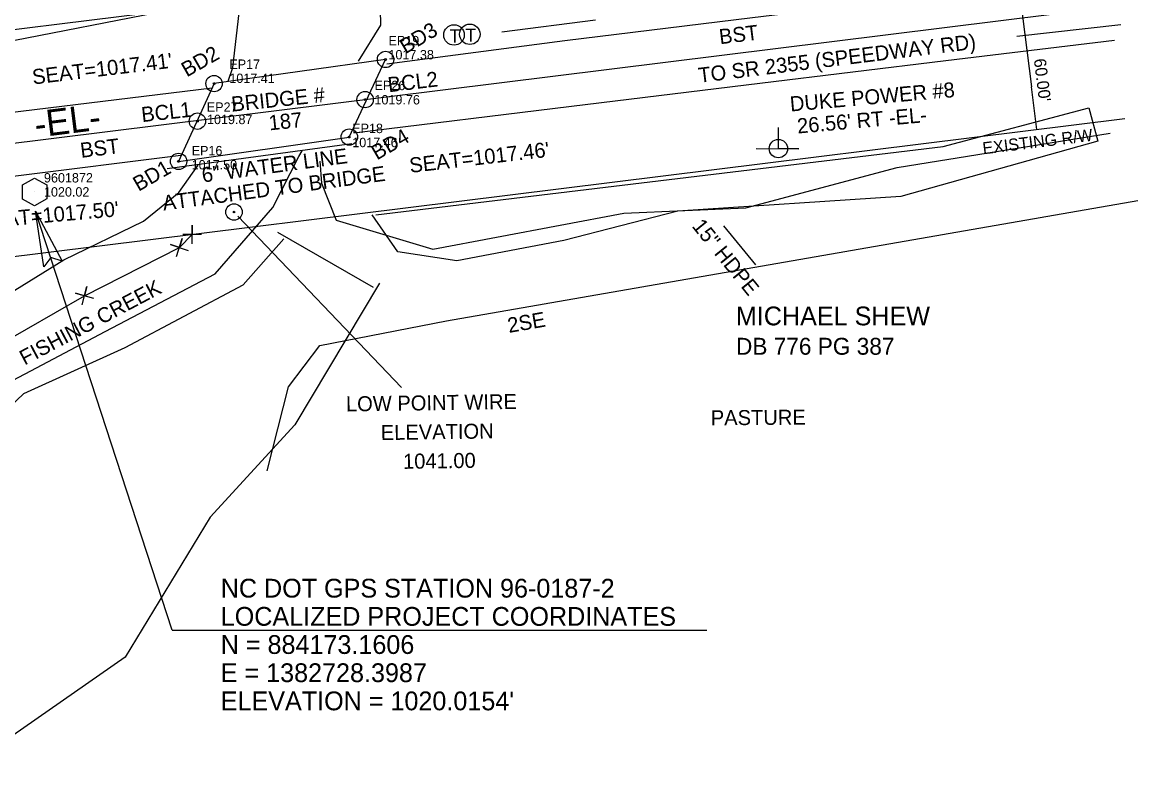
# Model space of a CAD drawing. Extents: x 1382088 to 1383563, y 883989 to 884716.
# Drawn here: x 1382725.1 to 1383021.8, y 884019.9 to 884218.3 of the extents above; entities that cross this region are included whole.
import ezdxf

# ---------------------------------------------------------------- set-up
doc = ezdxf.new("R2010")
doc.units = 0
for name, color, linetype in [('CTL GPS Vertical CELL', 7, 'Continuous'), ('CTL GPS Vertical Cogo Elevation', 7, 'Continuous'), ('CTL GPS Vertical Cogo Number', 7, 'Continuous'), ('CTL GPS Vertical Text', 7, 'Continuous'), ('Default', 7, 'Continuous'), ('Exist DTM Regular Point Cogo Elevation', 7, 'Continuous'), ('Exist DTM Regular Point Cogo Number', 7, 'Continuous'), ('Exist Horizontal Alignment', 7, 'Continuous'), ('Exist Horizontal Alignment Direction Label', 7, 'Continuous'), ('Exist Hydro Jurisdictional Stream or Body of Water', 7, 'Continuous'), ('Exist Hydro Jurisdictional Stream or Body of Water Text', 7, 'Continuous'), ('Exist Hydro Stream or Body of Water', 7, 'Continuous'), ('Exist Other Culture Fence Line', 7, 'Continuous'), ('Exist Other Culture Fence Line Text', 7, 'Continuous'), ('Exist Other Culture Located Object CELL', 7, 'Continuous'), ('Exist Other Culture Located Object Text', 7, 'Continuous'), ('Exist Property Corner CELL', 7, 'Continuous'), ('Exist Property Deed Book Text', 7, 'Continuous'), ('Exist Property Line', 7, 'Continuous'), ('Exist Property Owner Text', 7, 'Continuous'), ('Exist Right of Way Line', 7, 'Continuous'), ('Exist Right of Way Line Text', 7, 'Continuous'), ('Exist Right of Way Width CELL', 7, 'Continuous'), ('Exist Roads EOP', 7, 'Continuous'), ('Exist Roads EOP Leader', 7, 'Continuous'), ('Exist Roads EOP Text', 7, 'Continuous'), ('Exist Structure Major Bridge Seat Top Elevation', 7, 'Continuous'), ('Exist Structure Major Deck Tunnel Box Culvert', 7, 'Continuous'), ('Exist Structure Major Deck Tunnel Box Culvert Text', 7, 'Continuous'), ('Exist Structure Minor Pipes HDPE 15 Inch', 7, 'Continuous'), ('Exist Structure Minor Pipes HDPE 15 Inch Text', 7, 'Continuous'), ('Exist Utilities Other Located Object CELL', 7, 'Continuous'), ('Exist Utilities Other Located Object Leader', 7, 'Continuous'), ('Exist Utilities Other Located Object Text', 7, 'Continuous'), ('Exist Utilities Power Joint Use Telephone CELL', 7, 'Continuous'), ('Exist Utilities Power Joint Use Telephone Text', 7, 'Continuous'), ('Exist Utilities Sanitary Sewer Manhole Cogo Elevation', 7, 'Continuous'), ('Exist Utilities Sanitary Sewer Manhole Cogo Number', 7, 'Continuous'), ('Exist Utilities Telephone Manhole CELL', 7, 'Continuous'), ('Exist Utilities Telephone UG FO', 7, 'Continuous'), ('Exist Utilities Water AG Line', 7, 'Continuous'), ('Exist Utilities Water AG Line Text', 7, 'Continuous'), ('Exist Vegetation Woods Line', 7, 'Continuous'), ('Exist Vegetation Woods Line Text', 7, 'Continuous'), ('Old_Level_11', 7, 'Continuous')]:
    doc.layers.add(name, color=color, linetype=linetype)

# ---------------------------------------------------------------- blocks, each defined once
blk = doc.blocks.new('EXIST OTHER CULTURE LOCATED OBJECT')
at = {"layer": 'Exist Other Culture Located Object CELL'}
for radius in [0.0436, 0.0048]:
    blk.add_circle((0, 0), radius, dxfattribs=at)

msp = doc.modelspace()

# ---------------------------------------------------------------- linework, layer by layer
at = {"layer": 'CTL GPS Vertical CELL'}
msp.add_line((1382728.4, 884173.16), (1382728.4, 884173.16), dxfattribs=at)
msp.add_lwpolyline([(1382725.17, 884175.03), (1382728.42, 884176.84), (1382731.67, 884175.06), (1382731.62, 884171.33), (1382728.37, 884169.44), (1382725.17, 884171.26)], close=True, dxfattribs=at)
at = {"layer": 'Default'}
for q in [(1382728.65, 884168.01), (1382907.24, 884056.51)]:
    msp.add_line((1382764.99, 884056.51), q, dxfattribs=at)
at = {"layer": 'Exist Horizontal Alignment'}
msp.add_line((1382573.21, 884167.56), (1383014.71, 884222.44), dxfattribs=at)
at = {"layer": 'Exist Hydro Jurisdictional Stream or Body of Water'}
for points in [[(1382779.86, 884202.64), (1382781.14, 884206.31), (1382784.29, 884233.98), (1382796.55, 884263.54), (1382815.75, 884285.03)], [(1382814.54, 884207.97), (1382820.54, 884217.58), (1382820.04, 884238.41), (1382839.31, 884257.77), (1382850.16, 884274.58)], [(1382697.09, 884084.7), (1382707.03, 884107.53), (1382718.1, 884120.62), (1382747.18, 884136), (1382776.41, 884151.32), (1382791.76, 884168.97), (1382798.67, 884182.57), (1382799.6, 884184.06)], [(1382676.1, 884092.45), (1382689.38, 884112.63), (1382706.34, 884136.61), (1382736.2, 884155.04), (1382757.42, 884165.36), (1382766.78, 884172.98), (1382771.88, 884180.29)]]:
    msp.add_lwpolyline(points, dxfattribs=at)
at = {"layer": 'Exist Hydro Stream or Body of Water'}
msp.add_lwpolyline([(1382804.25, 884181.32), (1382804.73, 884175.5), (1382808.66, 884165.61), (1382834.38, 884157.94), (1382885.17, 884167.47), (1382917.56, 884168.91), (1382957.83, 884179.68), (1383014.49, 884188.81)], dxfattribs=at)
at = {"layer": 'Exist Other Culture Fence Line'}
msp.add_lwpolyline([(1382790.26, 884098.9), (1382795.98, 884121.25), (1382804.31, 884132.3), (1382837.93, 884138.79), (1383021.83, 884170.84)], dxfattribs=at)
at = {"layer": 'Exist Property Corner CELL'}
for p, q in [((1382770.33, 884161.83), (1382770.33, 884161.83)), ((1382766.92, 884158.34), (1382766.92, 884158.34)), ((1382741.69, 884145.52), (1382741.69, 884145.52))]:
    msp.add_line(p, q, dxfattribs=at)
for points in [[(1382770.36, 884159.33), (1382770.3, 884164.33), (1382770.33, 884161.83), (1382767.83, 884161.8), (1382772.83, 884161.86)], [(1382766.14, 884155.96), (1382767.69, 884160.72), (1382766.92, 884158.34), (1382764.54, 884159.12), (1382769.29, 884157.57)], [(1382741.03, 884143.11), (1382742.34, 884147.93), (1382741.69, 884145.52), (1382739.27, 884146.17), (1382744.1, 884144.86)]]:
    msp.add_lwpolyline(points, dxfattribs=at)
at = {"layer": 'Exist Property Line'}
for p, q in [((1382766.92, 884158.34), (1382770.33, 884161.83)), ((1382741.69, 884145.52), (1382766.92, 884158.34)), ((1382712.22, 884128.62), (1382741.69, 884145.52))]:
    msp.add_line(p, q, dxfattribs=at)
at = {"layer": 'Exist Right of Way Line'}
for p, q in [((1382569.51, 884197.33), (1383011.01, 884252.21)), ((1382576.91, 884137.79), (1383018.41, 884192.67))]:
    msp.add_line(p, q, dxfattribs=at)
at = {"layer": 'Exist Right of Way Width CELL'}
for p in [(1382987.58, 884249.3), (1382994.98, 884189.76)]:
    msp.add_line(p, (1382993.57, 884201.1), dxfattribs=at)
at = {"layer": 'Exist Roads EOP'}
for points in [[(1382822.11, 884207.29), (1382869.48, 884213.43), (1382919.36, 884219.54), (1382969.37, 884225.7), (1383013.63, 884231.16)], [(1382813.33, 884188.87), (1382871.2, 884195.99), (1382921.29, 884202.13), (1382970.84, 884208.1), (1383015.68, 884213.51)], [(1382572.45, 884176.87), (1382622.03, 884182.5), (1382672.6, 884188.52), (1382721.14, 884194.24), (1382775.67, 884200.85)], [(1382574.09, 884158.95), (1382623.82, 884164.93), (1382674.58, 884171.14), (1382723.43, 884177.39), (1382767.31, 884182.9)]]:
    msp.add_lwpolyline(points, dxfattribs=at)
at = {"layer": 'Exist Roads EOP Leader'}
msp.add_line((1383017.33, 884217.65), (1382989.66, 884214.49), dxfattribs=at)
at = {"layer": 'Exist Structure Major Deck Tunnel Box Culvert'}
msp.add_lwpolyline([(1382766.7, 884181.28), (1382812.12, 884187.76), (1382821.76, 884208.41), (1382776.14, 884201.99), (1382766.7, 884181.28)], dxfattribs=at)
at = {"layer": 'Exist Structure Minor Pipes HDPE 15 Inch'}
msp.add_lwpolyline([(1382911.65, 884164.16), (1382920.14, 884153.71)], dxfattribs=at)
at = {"layer": 'Exist Utilities Other Located Object CELL'}
for radius in [2.18, 0.24]:
    msp.add_circle((1382781.45, 884167.8), radius, dxfattribs=at)
at = {"layer": 'Exist Utilities Other Located Object Leader'}
msp.add_line((1382782.46, 884166.68), (1382826.04, 884121.05), dxfattribs=at)
at = {"layer": 'Exist Utilities Power Joint Use Telephone CELL'}
msp.add_line((1382926.26, 884184.67), (1382926.26, 884184.67), dxfattribs=at)
msp.add_lwpolyline([(1382920.32, 884184.67), (1382931.66, 884184.63), (1382926.26, 884184.65), (1382926.26, 884190.29)], dxfattribs=at)
msp.add_circle((1382926.26, 884184.68), 2.45, dxfattribs=at)
at = {"layer": 'Exist Utilities Telephone Manhole CELL'}
for centre in [(1382839.97, 884214.93), (1382844.18, 884215.11)]:
    msp.add_circle(centre, 2.72, dxfattribs=at)
at = {"layer": 'Exist Utilities Telephone UG FO'}
msp.add_lwpolyline([(1382852.69, 884215.72), (1382877.65, 884218.96)], dxfattribs=at)
at = {"layer": 'Exist Utilities Water AG Line'}
msp.add_line((1382763.71, 884179.41), (1382812.76, 884186.01), dxfattribs=at)
at = {"layer": 'Exist Vegetation Woods Line'}
for points in [[(1382816.76, 884294.12), (1382787.84, 884262.24), (1382774.61, 884223.48), (1382708.95, 884210.73), (1382567.82, 884198.87)], [(1382819.17, 884167.05), (1382970.1, 884185.2), (1383008.81, 884195.5), (1383011.26, 884186.67), (1382958.83, 884171.95), (1382899.53, 884168.03), (1382869.15, 884160.18), (1382840.73, 884154.78), (1382825.05, 884157.24), (1382818.19, 884167.05)], [(1382793.02, 884162.47), (1382818.5, 884147.76)], [(1382696.17, 884069.92), (1382708.42, 884103.27), (1382725.57, 884119.46), (1382752.52, 884131.73), (1382783.89, 884148.41), (1382794.67, 884160.67)], [(1382820.15, 884148.9), (1382797.61, 884111.12), (1382775.07, 884086.6), (1382752.52, 884049.31), (1382718.71, 884025.77), (1382700.09, 884019.88)]]:
    msp.add_lwpolyline(points, dxfattribs=at)
at = {"layer": 'Old_Level_11'}
msp.add_lwpolyline([(1382730.84, 884153.21), (1382728.65, 884168.01), (1382735.77, 884154.74), (1382732.69, 884155.71)], close=True, dxfattribs=at)

# ---------------------------------------------------------------- block references
at = {"layer": 'Exist Other Culture Located Object CELL', "xscale": 50, "yscale": 50}
for p in [(1382821.76, 884208.41), (1382776.14, 884201.99), (1382816.33, 884197.73), (1382771.71, 884191.98), (1382812.12, 884187.76), (1382766.7, 884181.28)]:
    msp.add_blockref('EXIST OTHER CULTURE LOCATED OBJECT', p, dxfattribs=at)

# ---------------------------------------------------------------- texts
at = {"layer": 'CTL GPS Vertical Cogo Elevation'}
msp.add_text('1020.02', height=2.5, dxfattribs=at).set_placement((1382730.9, 884171.91))
at = {"layer": 'CTL GPS Vertical Cogo Number'}
msp.add_text('9601872', height=2.5, dxfattribs=at).set_placement((1382730.9, 884175.66))
at = {"layer": 'CTL GPS Vertical Text'}
for s, p in [('NC DOT GPS STATION 96-0187-2', (1382777.92, 884065.17)), ('LOCALIZED PROJECT COORDINATES', (1382777.92, 884057.67)), ('N = 884173.1606', (1382777.92, 884050.17)), ('E = 1382728.3987', (1382777.92, 884042.67)), ("ELEVATION = 1020.0154'", (1382777.92, 884035.17))]:
    msp.add_text(s, height=5, rotation=359.9944, dxfattribs=at).set_placement(p)
at = {"layer": 'Exist DTM Regular Point Cogo Elevation'}
for s, p in [('1019.76', (1382818.81, 884196.44)), ('1019.87', (1382774.27, 884191.2))]:
    msp.add_text(s, height=2.5, dxfattribs=at).set_placement(p)
at = {"layer": 'Exist DTM Regular Point Cogo Number'}
for s, p in [('EP26', (1382818.84, 884200.24)), ('EP27', (1382774.21, 884194.48))]:
    msp.add_text(s, height=2.5, dxfattribs=at).set_placement(p)
at = {"layer": 'Exist Horizontal Alignment Direction Label'}
msp.add_text('-EL-', height=7, rotation=7.0864, dxfattribs=at).set_placement((1382728.79, 884187.58))
at = {"layer": 'Exist Hydro Jurisdictional Stream or Body of Water Text'}
msp.add_text('FISHING CREEK', height=4, rotation=27.8639, dxfattribs=at).set_placement((1382725.75, 884126.93))
at = {"layer": 'Exist Other Culture Fence Line Text'}
msp.add_text('2SE', height=4, rotation=9.8862, dxfattribs=at).set_placement((1382854.59, 884135.61))
at = {"layer": 'Exist Other Culture Located Object Text'}
for s, rotation, p in [('BD3', 30.7884, (1382827.06, 884209.78)), ('BD2', 29.7996, (1382768.91, 884203.62)), ('BCL2', 6.8455, (1382822.61, 884199.67)), ('BCL1', 6.2542, (1382757.01, 884191.72)), ('BD4', 30.1447, (1382819.47, 884181.51)), ('BD1', 30.0713, (1382756.06, 884173.17))]:
    msp.add_text(s, height=4, rotation=rotation, dxfattribs=at).set_placement(p)
at = {"layer": 'Exist Property Deed Book Text'}
msp.add_text('DB 776 PG 387', height=4.5, rotation=0, dxfattribs=at).set_placement((1382914.98, 884129.81))
at = {"layer": 'Exist Property Owner Text'}
msp.add_text('MICHAEL SHEW', height=5, rotation=0, dxfattribs=at).set_placement((1382914.95, 884137.63))
at = {"layer": 'Exist Right of Way Line Text'}
msp.add_text('EXISTING R/W', height=3.2, rotation=7.0864, dxfattribs=at).set_placement((1382980.76, 884183.15))
at = {"layer": 'Exist Right of Way Width CELL'}
msp.add_text("60.00'", height=3.2, rotation=277.0864, dxfattribs=at).set_placement((1382994.19, 884208.46))
at = {"layer": 'Exist Roads EOP Text'}
for s, rotation, p in [('TO SR 2355 (SPEEDWAY RD)', 7.0223, (1382905.23, 884202.18)), ('BST', 6.8712, (1382910.73, 884212.45)), ('BST', 6.9719, (1382740.8, 884182.21))]:
    msp.add_text(s, height=4, rotation=rotation, dxfattribs=at).set_placement(p)
at = {"layer": 'Exist Structure Major Bridge Seat Top Elevation'}
for s, rotation, p in [("SEAT=1017.41'", 6.8581, (1382728.01, 884201.74)), ("SEAT=1017.46'", 6.6179, (1382828.33, 884178.21)), ("SEAT=1017.50'", 5.0905, (1382713.66, 884163.37))]:
    msp.add_text(s, height=4, rotation=rotation, dxfattribs=at).set_placement(p)
at = {"layer": 'Exist Structure Major Deck Tunnel Box Culvert Text'}
for s, p in [('BRIDGE #', (1382780.96, 884194.51)), ('187', (1382790.89, 884189.52))]:
    msp.add_text(s, height=4, rotation=5.987, dxfattribs=at).set_placement(p)
at = {"layer": 'Exist Structure Minor Pipes HDPE 15 Inch Text'}
msp.add_text('15" HDPE', height=4, rotation=309.0956, dxfattribs=at).set_placement((1382903.09, 884163.98))
at = {"layer": 'Exist Utilities Other Located Object Text'}
for s, p in [('LOW POINT WIRE ', (1382811.26, 884114.69)), ('ELEVATION', (1382820.52, 884107.08)), ('1041.00', (1382826.44, 884099.42))]:
    msp.add_text(s, height=4, rotation=0.8742, dxfattribs=at).set_placement(p)
at = {"layer": 'Exist Utilities Power Joint Use Telephone Text'}
for s, p in [('DUKE POWER #8', (1382929.5, 884194.54)), ("26.56' RT -EL-", (1382931.41, 884188.69))]:
    msp.add_text(s, height=4, rotation=5.0691, dxfattribs=at).set_placement(p)
at = {"layer": 'Exist Utilities Sanitary Sewer Manhole Cogo Elevation'}
for s, p in [('1017.38', (1382822.54, 884208.43)), ('1017.41', (1382780.21, 884202.15)), ('1017.46', (1382812.9, 884185.06)), ('1017.50', (1382770.19, 884179.14))]:
    msp.add_text(s, height=2.5, dxfattribs=at).set_placement(p)
at = {"layer": 'Exist Utilities Sanitary Sewer Manhole Cogo Number'}
for s, p in [('EP19', (1382822.54, 884212.18)), ('EP17', (1382780.21, 884205.9)), ('EP18', (1382812.9, 884188.81)), ('EP16', (1382770.19, 884182.89))]:
    msp.add_text(s, height=2.5, dxfattribs=at).set_placement(p)
at = {"layer": 'Exist Utilities Telephone Manhole CELL'}
for p in [(1382838.8, 884212.92), (1382843.01, 884213.11)]:
    msp.add_text('T', height=3.5, dxfattribs=at).set_placement(p)
at = {"layer": 'Exist Utilities Water AG Line Text'}
for s, p in [('6" WATER LINE', (1382773.16, 884175.64)), ('ATTACHED TO BRIDGE', (1382762.72, 884168.18))]:
    msp.add_text(s, height=4, rotation=7.6576, dxfattribs=at).set_placement(p)
at = {"layer": 'Exist Vegetation Woods Line Text'}
msp.add_text('PASTURE', height=4, rotation=0.3979, dxfattribs=at).set_placement((1382908.29, 884111.02))

doc.saveas('drawing.dxf')
